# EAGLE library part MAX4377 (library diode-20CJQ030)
Maxim (www.maxim-ic.com) Dual High-Side Current-Sense Amplifier with Internal Gain (20, 50, 100X gain)
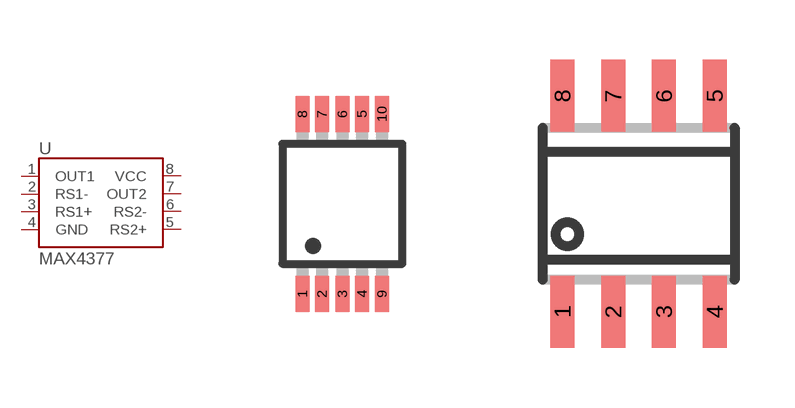
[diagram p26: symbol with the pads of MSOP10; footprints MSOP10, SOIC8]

Designator prefix U

## MAX4377U  [MSOP10]
1  OUT1  out
2  RS1-  pas
3  RS1+  pas
4  GND  pwr
5  RS2+  pas
6  RS2-  pas
7  OUT2  out
8  VCC  pwr

## MAX4377S  [SOIC8]
Pads as for MSOP10

## Footprint MSOP10 (pad centres in mm)
MSOP10
smd 0.35 x 0.9: 1 -1,-2.25; 2 -0.51,-2.25; 3 0,-2.25; 4 0.49,-2.25; 5 0.49,2.25; 6 0,2.25; 7 -0.51,2.25; 8 -1,2.25; 9 0.99,-2.25; 10 0.99,2.25

## Footprint SOIC8 (pad centres in mm)
Small Outline IC
smd 0.6 x 1.8: 1 -1.905,-2.7; 2 -0.635,-2.7; 3 0.635,-2.7; 4 1.905,-2.7; 5 1.905,2.7; 6 0.635,2.7; 7 -0.635,2.7; 8 -1.905,2.7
